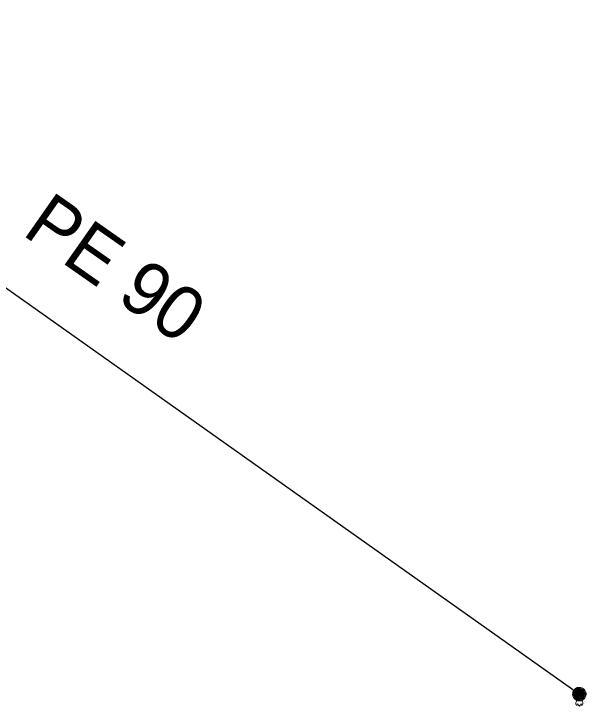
# Model space of a CAD drawing. Extents: x -683466 to -682479, y -996772 to -995963.
# Drawn here: x -682684.66 to -682673.94, y -996533.07 to -996520.1 of the extents above; entities that cross this region are included whole.
import ezdxf

# ---------------------------------------------------------------- set-up
doc = ezdxf.new("R2010")
doc.units = 0
doc.header["$LTSCALE"] = 0.4
doc.layers.add('1', color=7, linetype='Continuous')
doc.layers.add('17', color=7, linetype='Continuous', lineweight=25)
doc.layers.add('9', color=7, linetype='Continuous', lineweight=13)

msp = doc.modelspace()

# ---------------------------------------------------------------- linework, layer by layer
at = {"layer": '17'}
msp.add_line((-682692.053, -996520.101), (-682674.07, -996532.85), dxfattribs=at)
at = {"layer": '9'}
for points in [[(-682674.07, -996532.723), (-682674.083, -996532.723), (-682674.096, -996532.725), (-682674.109, -996532.728), (-682674.121, -996532.733), (-682674.133, -996532.739), (-682674.144, -996532.746), (-682674.154, -996532.754), (-682674.164, -996532.764), (-682674.172, -996532.774), (-682674.179, -996532.785), (-682674.185, -996532.797), (-682674.19, -996532.809), (-682674.193, -996532.822), (-682674.195, -996532.835), (-682674.197, -996532.848), (-682674.196, -996532.861), (-682674.194, -996532.874), (-682674.191, -996532.887), (-682674.186, -996532.899), (-682674.18, -996532.911), (-682674.173, -996532.922), (-682674.165, -996532.932), (-682674.155, -996532.942), (-682674.145, -996532.95), (-682674.134, -996532.957), (-682674.122, -996532.963), (-682674.11, -996532.968), (-682674.097, -996532.971), (-682674.084, -996532.973), (-682674.071, -996532.975), (-682674.058, -996532.975), (-682674.045, -996532.973), (-682674.032, -996532.97), (-682674.02, -996532.965), (-682674.008, -996532.959), (-682673.997, -996532.952), (-682673.987, -996532.944), (-682673.977, -996532.934), (-682673.969, -996532.924), (-682673.962, -996532.913), (-682673.956, -996532.901), (-682673.951, -996532.889), (-682673.948, -996532.876), (-682673.946, -996532.863), (-682673.945, -996532.85), (-682673.945, -996532.837), (-682673.947, -996532.824), (-682673.95, -996532.811), (-682673.955, -996532.799), (-682673.961, -996532.787), (-682673.968, -996532.776), (-682673.976, -996532.766), (-682673.986, -996532.756), (-682673.996, -996532.748), (-682674.007, -996532.741), (-682674.019, -996532.735), (-682674.031, -996532.73), (-682674.044, -996532.727), (-682674.057, -996532.725)], [(-682674.07, -996532.977), (-682674.057, -996532.976), (-682674.044, -996532.974), (-682674.031, -996532.971), (-682674.019, -996532.966), (-682674.007, -996532.96), (-682673.996, -996532.953), (-682673.986, -996532.945), (-682673.976, -996532.935), (-682673.968, -996532.925), (-682673.961, -996532.914), (-682673.955, -996532.902), (-682673.95, -996532.89), (-682673.947, -996532.877), (-682673.945, -996532.864), (-682673.944, -996532.851), (-682673.943, -996532.838), (-682673.945, -996532.825), (-682673.948, -996532.812), (-682673.953, -996532.8), (-682673.959, -996532.788), (-682673.966, -996532.777), (-682673.974, -996532.767), (-682673.984, -996532.757), (-682673.994, -996532.749), (-682674.005, -996532.742), (-682674.017, -996532.736), (-682674.029, -996532.731), (-682674.042, -996532.728), (-682674.055, -996532.726), (-682674.068, -996532.725), (-682674.081, -996532.725), (-682674.094, -996532.727), (-682674.107, -996532.73), (-682674.119, -996532.735), (-682674.131, -996532.741), (-682674.142, -996532.748), (-682674.152, -996532.756), (-682674.162, -996532.766), (-682674.17, -996532.776), (-682674.177, -996532.787), (-682674.183, -996532.799), (-682674.188, -996532.811), (-682674.191, -996532.824), (-682674.193, -996532.837), (-682674.196, -996532.85), (-682674.195, -996532.863), (-682674.193, -996532.876), (-682674.19, -996532.889), (-682674.185, -996532.901), (-682674.179, -996532.913), (-682674.172, -996532.924), (-682674.164, -996532.934), (-682674.154, -996532.944), (-682674.144, -996532.952), (-682674.133, -996532.959), (-682674.121, -996532.965), (-682674.109, -996532.97), (-682674.096, -996532.973), (-682674.083, -996532.975)], [(-682674.07, -996532.744), (-682674.081, -996532.742), (-682674.092, -996532.744), (-682674.103, -996532.747), (-682674.113, -996532.751), (-682674.123, -996532.756), (-682674.132, -996532.762), (-682674.141, -996532.769), (-682674.149, -996532.777), (-682674.156, -996532.786), (-682674.162, -996532.795), (-682674.167, -996532.805), (-682674.171, -996532.815), (-682674.174, -996532.826), (-682674.177, -996532.837), (-682674.177, -996532.848), (-682674.177, -996532.859), (-682674.175, -996532.87), (-682674.172, -996532.881), (-682674.168, -996532.891), (-682674.163, -996532.901), (-682674.157, -996532.91), (-682674.15, -996532.919), (-682674.142, -996532.927), (-682674.133, -996532.934), (-682674.124, -996532.94), (-682674.114, -996532.945), (-682674.104, -996532.949), (-682674.093, -996532.952), (-682674.082, -996532.954), (-682674.071, -996532.955), (-682674.06, -996532.956), (-682674.049, -996532.954), (-682674.038, -996532.951), (-682674.028, -996532.947), (-682674.018, -996532.942), (-682674.009, -996532.936), (-682674, -996532.929), (-682673.992, -996532.921), (-682673.985, -996532.912), (-682673.979, -996532.903), (-682673.974, -996532.893), (-682673.97, -996532.883), (-682673.967, -996532.872), (-682673.965, -996532.861), (-682673.965, -996532.85), (-682673.964, -996532.839), (-682673.966, -996532.828), (-682673.969, -996532.817), (-682673.973, -996532.807), (-682673.978, -996532.797), (-682673.984, -996532.788), (-682673.991, -996532.779), (-682673.999, -996532.771), (-682674.008, -996532.764), (-682674.017, -996532.758), (-682674.027, -996532.753), (-682674.037, -996532.749), (-682674.048, -996532.746), (-682674.059, -996532.744)], [(-682674.07, -996532.957), (-682674.059, -996532.957), (-682674.048, -996532.955), (-682674.037, -996532.952), (-682674.027, -996532.948), (-682674.017, -996532.943), (-682674.008, -996532.937), (-682673.999, -996532.93), (-682673.991, -996532.922), (-682673.984, -996532.913), (-682673.978, -996532.904), (-682673.973, -996532.894), (-682673.969, -996532.884), (-682673.966, -996532.873), (-682673.964, -996532.862), (-682673.964, -996532.851), (-682673.962, -996532.84), (-682673.964, -996532.829), (-682673.967, -996532.818), (-682673.971, -996532.808), (-682673.976, -996532.798), (-682673.982, -996532.789), (-682673.989, -996532.78), (-682673.997, -996532.772), (-682674.006, -996532.765), (-682674.015, -996532.759), (-682674.025, -996532.754), (-682674.035, -996532.75), (-682674.046, -996532.747), (-682674.057, -996532.745), (-682674.068, -996532.745), (-682674.079, -996532.744), (-682674.09, -996532.746), (-682674.101, -996532.749), (-682674.111, -996532.753), (-682674.121, -996532.758), (-682674.13, -996532.764), (-682674.139, -996532.771), (-682674.147, -996532.779), (-682674.154, -996532.788), (-682674.16, -996532.797), (-682674.165, -996532.807), (-682674.169, -996532.817), (-682674.172, -996532.828), (-682674.174, -996532.839), (-682674.176, -996532.85), (-682674.176, -996532.861), (-682674.174, -996532.872), (-682674.171, -996532.883), (-682674.167, -996532.893), (-682674.162, -996532.903), (-682674.156, -996532.912), (-682674.149, -996532.921), (-682674.141, -996532.929), (-682674.132, -996532.936), (-682674.123, -996532.942), (-682674.113, -996532.947), (-682674.103, -996532.951), (-682674.092, -996532.954), (-682674.081, -996532.956)], [(-682674.07, -996532.762), (-682674.079, -996532.762), (-682674.088, -996532.763), (-682674.097, -996532.766), (-682674.105, -996532.769), (-682674.113, -996532.773), (-682674.121, -996532.778), (-682674.128, -996532.784), (-682674.134, -996532.79), (-682674.14, -996532.797), (-682674.145, -996532.805), (-682674.149, -996532.813), (-682674.152, -996532.821), (-682674.155, -996532.83), (-682674.156, -996532.839), (-682674.158, -996532.848), (-682674.157, -996532.857), (-682674.156, -996532.866), (-682674.153, -996532.875), (-682674.15, -996532.883), (-682674.146, -996532.891), (-682674.141, -996532.899), (-682674.135, -996532.906), (-682674.129, -996532.912), (-682674.122, -996532.918), (-682674.114, -996532.923), (-682674.106, -996532.927), (-682674.098, -996532.93), (-682674.089, -996532.933), (-682674.08, -996532.934), (-682674.071, -996532.936), (-682674.062, -996532.936), (-682674.053, -996532.935), (-682674.044, -996532.932), (-682674.036, -996532.929), (-682674.028, -996532.925), (-682674.02, -996532.92), (-682674.013, -996532.914), (-682674.007, -996532.908), (-682674.001, -996532.901), (-682673.996, -996532.893), (-682673.992, -996532.885), (-682673.989, -996532.877), (-682673.986, -996532.868), (-682673.985, -996532.859), (-682673.984, -996532.85), (-682673.984, -996532.841), (-682673.985, -996532.832), (-682673.988, -996532.823), (-682673.991, -996532.815), (-682673.995, -996532.807), (-682674, -996532.799), (-682674.006, -996532.792), (-682674.012, -996532.786), (-682674.019, -996532.78), (-682674.027, -996532.775), (-682674.035, -996532.771), (-682674.043, -996532.768), (-682674.052, -996532.765), (-682674.061, -996532.764)], [(-682674.07, -996532.938), (-682674.061, -996532.937), (-682674.052, -996532.936), (-682674.043, -996532.933), (-682674.035, -996532.93), (-682674.027, -996532.926), (-682674.019, -996532.921), (-682674.012, -996532.915), (-682674.006, -996532.909), (-682674, -996532.902), (-682673.995, -996532.894), (-682673.991, -996532.886), (-682673.988, -996532.878), (-682673.985, -996532.869), (-682673.984, -996532.86), (-682673.983, -996532.851), (-682673.982, -996532.842), (-682673.983, -996532.833), (-682673.986, -996532.824), (-682673.989, -996532.816), (-682673.993, -996532.808), (-682673.998, -996532.8), (-682674.004, -996532.793), (-682674.01, -996532.787), (-682674.017, -996532.781), (-682674.025, -996532.776), (-682674.033, -996532.772), (-682674.041, -996532.769), (-682674.05, -996532.766), (-682674.059, -996532.765), (-682674.068, -996532.764), (-682674.077, -996532.764), (-682674.086, -996532.765), (-682674.095, -996532.768), (-682674.103, -996532.771), (-682674.111, -996532.775), (-682674.119, -996532.78), (-682674.126, -996532.786), (-682674.132, -996532.792), (-682674.138, -996532.799), (-682674.143, -996532.807), (-682674.147, -996532.815), (-682674.15, -996532.823), (-682674.153, -996532.832), (-682674.154, -996532.841), (-682674.157, -996532.85), (-682674.156, -996532.859), (-682674.155, -996532.868), (-682674.152, -996532.877), (-682674.149, -996532.885), (-682674.145, -996532.893), (-682674.14, -996532.901), (-682674.134, -996532.908), (-682674.128, -996532.914), (-682674.121, -996532.92), (-682674.113, -996532.925), (-682674.105, -996532.929), (-682674.097, -996532.932), (-682674.088, -996532.935), (-682674.079, -996532.936)], [(-682674.07, -996532.782), (-682674.077, -996532.782), (-682674.084, -996532.783), (-682674.091, -996532.784), (-682674.097, -996532.787), (-682674.103, -996532.79), (-682674.109, -996532.794), (-682674.115, -996532.798), (-682674.12, -996532.803), (-682674.124, -996532.809), (-682674.128, -996532.815), (-682674.131, -996532.821), (-682674.134, -996532.827), (-682674.135, -996532.834), (-682674.138, -996532.841), (-682674.138, -996532.848), (-682674.138, -996532.855), (-682674.136, -996532.862), (-682674.135, -996532.869), (-682674.132, -996532.875), (-682674.129, -996532.882), (-682674.125, -996532.887), (-682674.121, -996532.893), (-682674.116, -996532.898), (-682674.11, -996532.902), (-682674.104, -996532.906), (-682674.098, -996532.909), (-682674.092, -996532.912), (-682674.085, -996532.914), (-682674.078, -996532.915), (-682674.071, -996532.916), (-682674.064, -996532.917), (-682674.057, -996532.916), (-682674.05, -996532.914), (-682674.044, -996532.911), (-682674.037, -996532.908), (-682674.032, -996532.904), (-682674.026, -996532.9), (-682674.021, -996532.895), (-682674.017, -996532.889), (-682674.013, -996532.884), (-682674.01, -996532.877), (-682674.007, -996532.871), (-682674.005, -996532.864), (-682674.004, -996532.857), (-682674.004, -996532.85), (-682674.004, -996532.843), (-682674.004, -996532.836), (-682674.006, -996532.829), (-682674.009, -996532.823), (-682674.012, -996532.817), (-682674.016, -996532.811), (-682674.02, -996532.805), (-682674.025, -996532.8), (-682674.031, -996532.796), (-682674.036, -996532.792), (-682674.043, -996532.789), (-682674.049, -996532.786), (-682674.056, -996532.785), (-682674.063, -996532.783)], [(-682674.07, -996532.918), (-682674.063, -996532.918), (-682674.056, -996532.916), (-682674.049, -996532.915), (-682674.043, -996532.912), (-682674.037, -996532.909), (-682674.031, -996532.905), (-682674.025, -996532.901), (-682674.02, -996532.896), (-682674.016, -996532.89), (-682674.012, -996532.884), (-682674.009, -996532.878), (-682674.006, -996532.872), (-682674.005, -996532.865), (-682674.003, -996532.858), (-682674.003, -996532.851), (-682674.001, -996532.844), (-682674.003, -996532.837), (-682674.004, -996532.83), (-682674.007, -996532.824), (-682674.01, -996532.817), (-682674.014, -996532.812), (-682674.018, -996532.806), (-682674.023, -996532.801), (-682674.029, -996532.797), (-682674.035, -996532.793), (-682674.041, -996532.79), (-682674.047, -996532.787), (-682674.054, -996532.785), (-682674.061, -996532.784), (-682674.068, -996532.784), (-682674.075, -996532.783), (-682674.082, -996532.784), (-682674.089, -996532.786), (-682674.095, -996532.789), (-682674.102, -996532.792), (-682674.107, -996532.796), (-682674.113, -996532.8), (-682674.118, -996532.805), (-682674.122, -996532.811), (-682674.126, -996532.816), (-682674.129, -996532.823), (-682674.132, -996532.829), (-682674.134, -996532.836), (-682674.135, -996532.843), (-682674.137, -996532.85), (-682674.137, -996532.857), (-682674.136, -996532.864), (-682674.134, -996532.871), (-682674.131, -996532.877), (-682674.128, -996532.883), (-682674.124, -996532.889), (-682674.12, -996532.895), (-682674.115, -996532.9), (-682674.109, -996532.904), (-682674.104, -996532.908), (-682674.097, -996532.911), (-682674.091, -996532.914), (-682674.084, -996532.915), (-682674.077, -996532.917)], [(-682674.07, -996532.803), (-682674.075, -996532.802), (-682674.08, -996532.802), (-682674.085, -996532.803), (-682674.089, -996532.805), (-682674.094, -996532.807), (-682674.098, -996532.81), (-682674.101, -996532.813), (-682674.105, -996532.817), (-682674.108, -996532.82), (-682674.111, -996532.824), (-682674.113, -996532.829), (-682674.115, -996532.833), (-682674.116, -996532.838), (-682674.118, -996532.843), (-682674.118, -996532.848), (-682674.118, -996532.853), (-682674.117, -996532.858), (-682674.116, -996532.863), (-682674.114, -996532.867), (-682674.112, -996532.872), (-682674.109, -996532.876), (-682674.106, -996532.88), (-682674.102, -996532.883), (-682674.099, -996532.886), (-682674.095, -996532.889), (-682674.09, -996532.891), (-682674.086, -996532.893), (-682674.081, -996532.894), (-682674.076, -996532.895), (-682674.071, -996532.896), (-682674.066, -996532.897), (-682674.061, -996532.896), (-682674.056, -996532.895), (-682674.052, -996532.893), (-682674.047, -996532.891), (-682674.043, -996532.888), (-682674.039, -996532.885), (-682674.036, -996532.882), (-682674.033, -996532.878), (-682674.03, -996532.874), (-682674.028, -996532.869), (-682674.026, -996532.865), (-682674.025, -996532.86), (-682674.024, -996532.855), (-682674.024, -996532.85), (-682674.024, -996532.845), (-682674.025, -996532.84), (-682674.025, -996532.835), (-682674.027, -996532.831), (-682674.029, -996532.826), (-682674.032, -996532.822), (-682674.035, -996532.819), (-682674.038, -996532.815), (-682674.042, -996532.812), (-682674.046, -996532.809), (-682674.051, -996532.807), (-682674.055, -996532.805), (-682674.06, -996532.804), (-682674.065, -996532.803)], [(-682674.07, -996532.898), (-682674.065, -996532.898), (-682674.06, -996532.897), (-682674.055, -996532.896), (-682674.051, -996532.894), (-682674.046, -996532.892), (-682674.042, -996532.889), (-682674.039, -996532.886), (-682674.035, -996532.882), (-682674.032, -996532.879), (-682674.029, -996532.875), (-682674.027, -996532.87), (-682674.025, -996532.866), (-682674.024, -996532.861), (-682674.023, -996532.856), (-682674.023, -996532.851), (-682674.021, -996532.846), (-682674.022, -996532.841), (-682674.023, -996532.836), (-682674.025, -996532.832), (-682674.027, -996532.827), (-682674.03, -996532.823), (-682674.033, -996532.819), (-682674.037, -996532.816), (-682674.04, -996532.813), (-682674.044, -996532.81), (-682674.049, -996532.808), (-682674.053, -996532.806), (-682674.058, -996532.805), (-682674.063, -996532.804), (-682674.068, -996532.804), (-682674.073, -996532.803), (-682674.078, -996532.804), (-682674.083, -996532.805), (-682674.087, -996532.807), (-682674.092, -996532.809), (-682674.096, -996532.812), (-682674.1, -996532.815), (-682674.103, -996532.818), (-682674.106, -996532.822), (-682674.109, -996532.826), (-682674.111, -996532.831), (-682674.113, -996532.835), (-682674.114, -996532.84), (-682674.115, -996532.845), (-682674.117, -996532.85), (-682674.117, -996532.855), (-682674.116, -996532.86), (-682674.115, -996532.865), (-682674.113, -996532.869), (-682674.111, -996532.874), (-682674.108, -996532.878), (-682674.105, -996532.881), (-682674.102, -996532.885), (-682674.098, -996532.888), (-682674.094, -996532.891), (-682674.089, -996532.893), (-682674.085, -996532.895), (-682674.08, -996532.896), (-682674.075, -996532.897)], [(-682674.07, -996532.823), (-682674.073, -996532.822), (-682674.076, -996532.821), (-682674.078, -996532.822), (-682674.081, -996532.823), (-682674.084, -996532.824), (-682674.086, -996532.826), (-682674.088, -996532.828), (-682674.09, -996532.83), (-682674.092, -996532.832), (-682674.094, -996532.834), (-682674.096, -996532.837), (-682674.097, -996532.84), (-682674.097, -996532.842), (-682674.098, -996532.845), (-682674.098, -996532.848), (-682674.098, -996532.851), (-682674.098, -996532.854), (-682674.097, -996532.857), (-682674.096, -996532.859), (-682674.095, -996532.862), (-682674.093, -996532.864), (-682674.091, -996532.867), (-682674.089, -996532.869), (-682674.087, -996532.87), (-682674.085, -996532.872), (-682674.082, -996532.873), (-682674.079, -996532.875), (-682674.077, -996532.875), (-682674.074, -996532.876), (-682674.071, -996532.877), (-682674.068, -996532.877), (-682674.065, -996532.877), (-682674.062, -996532.876), (-682674.06, -996532.875), (-682674.057, -996532.874), (-682674.055, -996532.872), (-682674.052, -996532.871), (-682674.05, -996532.869), (-682674.049, -996532.866), (-682674.047, -996532.864), (-682674.046, -996532.861), (-682674.045, -996532.859), (-682674.044, -996532.856), (-682674.044, -996532.853), (-682674.043, -996532.85), (-682674.044, -996532.847), (-682674.043, -996532.844), (-682674.045, -996532.842), (-682674.045, -996532.839), (-682674.046, -996532.836), (-682674.048, -996532.834), (-682674.049, -996532.832), (-682674.051, -996532.83), (-682674.054, -996532.828), (-682674.056, -996532.826), (-682674.059, -996532.825), (-682674.061, -996532.824), (-682674.064, -996532.823), (-682674.067, -996532.823)], [(-682674.07, -996532.878), (-682674.067, -996532.878), (-682674.064, -996532.878), (-682674.062, -996532.877), (-682674.059, -996532.876), (-682674.056, -996532.875), (-682674.054, -996532.873), (-682674.052, -996532.871), (-682674.05, -996532.869), (-682674.048, -996532.867), (-682674.046, -996532.865), (-682674.045, -996532.862), (-682674.044, -996532.859), (-682674.043, -996532.857), (-682674.043, -996532.854), (-682674.043, -996532.851), (-682674.041, -996532.848), (-682674.041, -996532.845), (-682674.042, -996532.842), (-682674.043, -996532.84), (-682674.044, -996532.837), (-682674.046, -996532.835), (-682674.048, -996532.832), (-682674.05, -996532.83), (-682674.052, -996532.829), (-682674.054, -996532.827), (-682674.057, -996532.826), (-682674.06, -996532.825), (-682674.062, -996532.824), (-682674.065, -996532.824), (-682674.068, -996532.823), (-682674.071, -996532.823), (-682674.074, -996532.823), (-682674.077, -996532.824), (-682674.079, -996532.825), (-682674.082, -996532.826), (-682674.084, -996532.828), (-682674.087, -996532.829), (-682674.089, -996532.831), (-682674.09, -996532.834), (-682674.092, -996532.836), (-682674.093, -996532.839), (-682674.094, -996532.841), (-682674.095, -996532.844), (-682674.095, -996532.847), (-682674.098, -996532.85), (-682674.097, -996532.853), (-682674.097, -996532.856), (-682674.096, -996532.858), (-682674.095, -996532.861), (-682674.094, -996532.864), (-682674.092, -996532.866), (-682674.091, -996532.868), (-682674.089, -996532.87), (-682674.086, -996532.872), (-682674.084, -996532.874), (-682674.081, -996532.875), (-682674.079, -996532.876), (-682674.076, -996532.877), (-682674.073, -996532.877)], [(-682674.07, -996532.842), (-682674.072, -996532.841), (-682674.072, -996532.841), (-682674.072, -996532.842), (-682674.074, -996532.842), (-682674.075, -996532.841), (-682674.075, -996532.843), (-682674.075, -996532.843), (-682674.077, -996532.843), (-682674.077, -996532.843), (-682674.078, -996532.844), (-682674.078, -996532.846), (-682674.078, -996532.846), (-682674.079, -996532.846), (-682674.079, -996532.848), (-682674.079, -996532.848), (-682674.079, -996532.849), (-682674.079, -996532.85), (-682674.078, -996532.85), (-682674.078, -996532.851), (-682674.078, -996532.853), (-682674.077, -996532.853), (-682674.077, -996532.853), (-682674.076, -996532.854), (-682674.076, -996532.854), (-682674.075, -996532.856), (-682674.074, -996532.856), (-682674.073, -996532.857), (-682674.073, -996532.857), (-682674.072, -996532.857), (-682674.071, -996532.857), (-682674.07, -996532.858), (-682674.069, -996532.858), (-682674.069, -996532.858), (-682674.068, -996532.857), (-682674.067, -996532.857), (-682674.066, -996532.856), (-682674.066, -996532.856), (-682674.065, -996532.855), (-682674.065, -996532.855), (-682674.064, -996532.854), (-682674.064, -996532.853), (-682674.063, -996532.852), (-682674.063, -996532.852), (-682674.063, -996532.851), (-682674.063, -996532.85), (-682674.063, -996532.849), (-682674.063, -996532.848), (-682674.063, -996532.848), (-682674.064, -996532.847), (-682674.063, -996532.846), (-682674.065, -996532.845), (-682674.065, -996532.845), (-682674.065, -996532.844), (-682674.065, -996532.844), (-682674.067, -996532.843), (-682674.068, -996532.843), (-682674.069, -996532.843), (-682674.069, -996532.842), (-682674.07, -996532.842)], [(-682674.07, -996532.859), (-682674.069, -996532.859), (-682674.068, -996532.859), (-682674.068, -996532.858), (-682674.067, -996532.858), (-682674.066, -996532.858), (-682674.065, -996532.857), (-682674.065, -996532.857), (-682674.064, -996532.856), (-682674.064, -996532.856), (-682674.063, -996532.855), (-682674.063, -996532.854), (-682674.063, -996532.853), (-682674.062, -996532.853), (-682674.062, -996532.852), (-682674.062, -996532.851), (-682674.061, -996532.85), (-682674.061, -996532.849), (-682674.063, -996532.849), (-682674.062, -996532.848), (-682674.061, -996532.847), (-682674.062, -996532.846), (-682674.062, -996532.846), (-682674.063, -996532.845), (-682674.063, -996532.845), (-682674.064, -996532.844), (-682674.065, -996532.844), (-682674.066, -996532.843), (-682674.066, -996532.843), (-682674.067, -996532.843), (-682674.068, -996532.843), (-682674.069, -996532.843), (-682674.07, -996532.843), (-682674.07, -996532.843), (-682674.071, -996532.843), (-682674.072, -996532.843), (-682674.073, -996532.844), (-682674.073, -996532.844), (-682674.074, -996532.845), (-682674.074, -996532.845), (-682674.075, -996532.846), (-682674.075, -996532.847), (-682674.077, -996532.848), (-682674.077, -996532.848), (-682674.078, -996532.849), (-682674.078, -996532.85), (-682674.078, -996532.851), (-682674.078, -996532.852), (-682674.078, -996532.852), (-682674.077, -996532.853), (-682674.077, -996532.854), (-682674.076, -996532.855), (-682674.076, -996532.855), (-682674.075, -996532.856), (-682674.075, -996532.856), (-682674.074, -996532.857), (-682674.073, -996532.857), (-682674.072, -996532.857), (-682674.072, -996532.858), (-682674.071, -996532.858)]]:
    msp.add_lwpolyline(points, close=True, dxfattribs=at)
for points in [[(-682674.124, -996533.062), (-682674.136, -996533.036), (-682674.136, -996533.009), (-682674.124, -996532.983), (-682674.109, -996532.97)], [(-682674.097, -996533.032), (-682674.117, -996533.056), (-682674.124, -996533.062)], [(-682674.097, -996533.032), (-682674.087, -996533.058), (-682674.07, -996533.075)], [(-682674.043, -996533.032), (-682674.052, -996533.058), (-682674.07, -996533.075)], [(-682674.043, -996533.032), (-682674.023, -996533.056), (-682674.015, -996533.062)], [(-682674.015, -996533.062), (-682674.004, -996533.036), (-682674.004, -996533.009), (-682674.016, -996532.983), (-682674.03, -996532.97)]]:
    msp.add_lwpolyline(points, dxfattribs=at)

# ---------------------------------------------------------------- texts
at = {"layer": '1'}
msp.add_text('PE 90 ', height=1, rotation=325, dxfattribs=at).set_placement((-682684.53, -996524.226))

doc.saveas('drawing.dxf')
